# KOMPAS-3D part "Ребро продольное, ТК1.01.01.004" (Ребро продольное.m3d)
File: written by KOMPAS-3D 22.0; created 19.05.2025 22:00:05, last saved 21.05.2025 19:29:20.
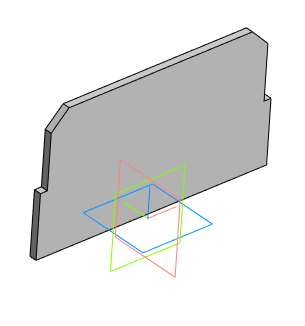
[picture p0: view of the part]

Document properties: Автор: user; Полное имя файла: КД\Чертеж Ребро продольное.cdw

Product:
- Part/product: Ребро продольное  | designation ТК1.01.01.004
    Масса: 0.575358
    Форматы листов документа: A3
- Part/product: Ребро продольное  | designation ТК1.01.01.004-01
    Масса: 0.574941
    Форматы листов документа: A4
    source file: Ребро продольное _ -01.cdw

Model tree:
1. Эскиз:1
2. Элемент выдавливания:1
     Расстояние 1 = 5
3. Элемент выдавливания:4  (with: Элемент выдавливания:1)
     Расстояние 2 = 5
4. Эскиз:2  (with: Элемент выдавливания:1)
5. Элемент выдавливания:5
     Расстояние 2 = 5
6. Эскиз:3  (with: Элемент выдавливания:1)
7. Элемент выдавливания:6
     Расстояние 2 = 5
8. Элемент выдавливания:2  (with: Элемент выдавливания:1)
     Расстояние 2 = 5
9. Элемент выдавливания:3
     Расстояние 2 = 5
10. Фаска:1  (with: Элемент выдавливания:4)
     Угол = 45; Длина 1 = 10; Длина 2 = 10
11. Элемент выдавливания:7  (with: Элемент выдавливания:4)
     Расстояние 1 = 5
12. Фаска:2  (with: Элемент выдавливания:7)
     Угол = 45; Длина 1 = 12; Длина 2 = 12
13. Фаска:3  (with: Элемент выдавливания:7)
     Угол = 45; Длина 1 = 12; Длина 2 = 12

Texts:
  ТК1.01.01.004
  ТК1.01.01.004-01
